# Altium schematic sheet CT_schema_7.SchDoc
size 277 x 170 mm
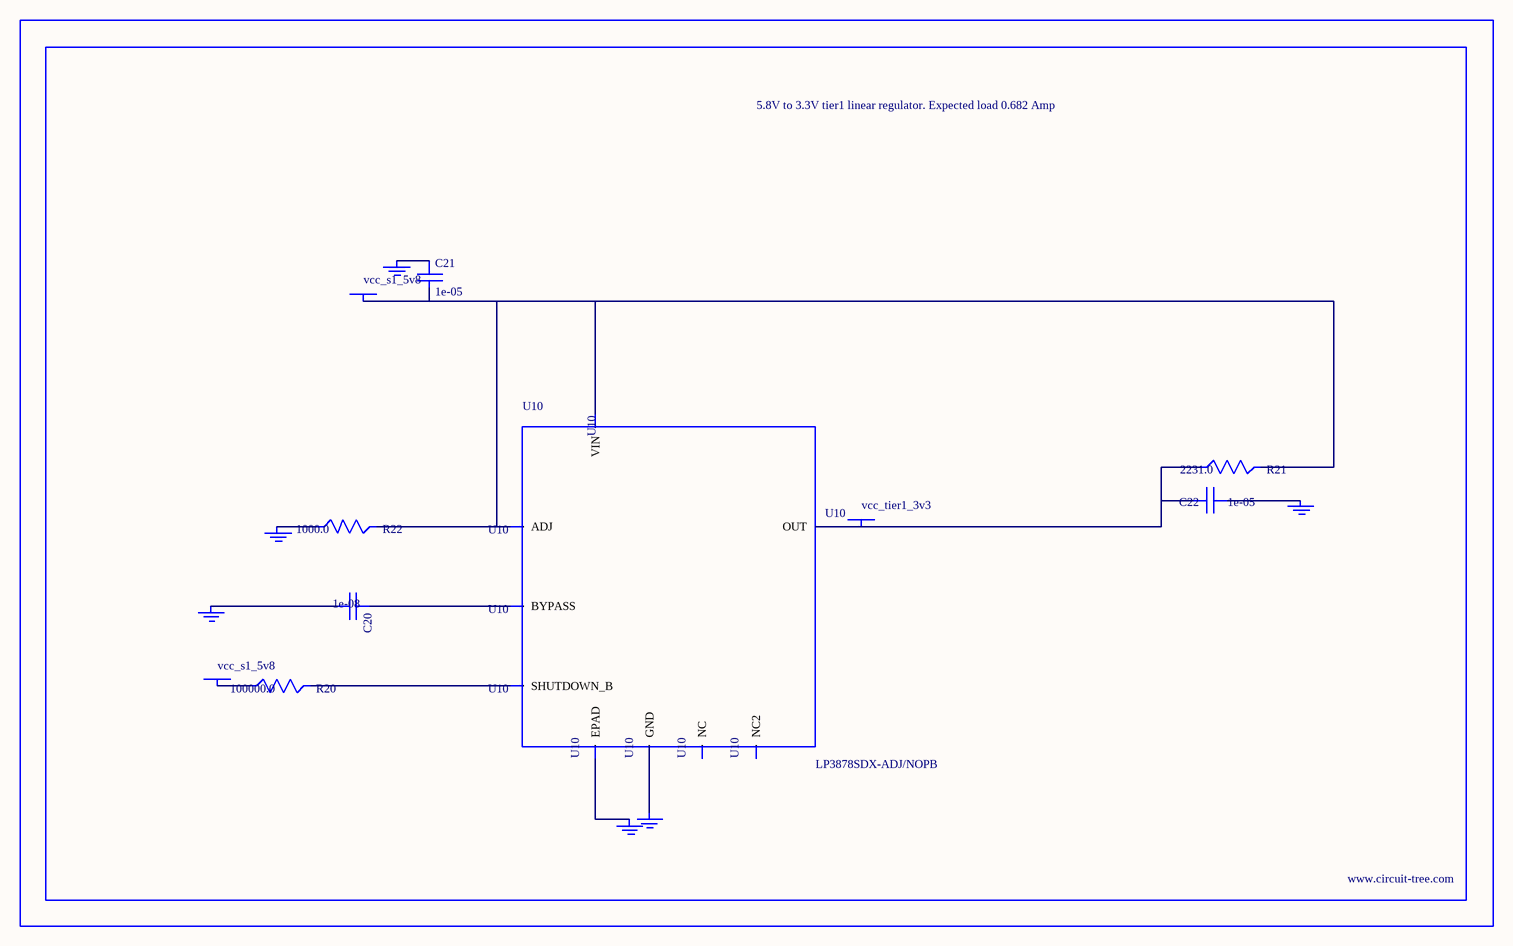
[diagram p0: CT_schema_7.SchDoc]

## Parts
BORDER6  (no value)
C20  1e-08  [C0402]
C21  1e-05  [C1206]
C22  1e-05  [C1210]
GND_INSTANCE_6_0  (no value)
GND_INSTANCE_6_1  (no value)
GND_INSTANCE_6_2  (no value)
GND_INSTANCE_6_3  (no value)
GND_INSTANCE_6_4  (no value)
GND_INSTANCE_6_5  (no value)
POWER_INSTANCE_6_0  vcc_s1_5v8
POWER_INSTANCE_6_1  vcc_s1_5v8
POWER_INSTANCE_6_2  vcc_tier1_3v3
R20  100000.0  [R0603]
R21  2231.0  [R0603]
R22  1000.0  [R0603]
U10  LP3878SDX-ADJ/NOPB  [WSON-8]

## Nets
NetC20_1: C20.1 U10.1(BYPASS)
NetC20_2: C20.2 GND_INSTANCE_6_0.0(GND)
NetC21_1: C21.1 GND_INSTANCE_6_1.0(GND)
NetC21_2: C21.2 POWER_INSTANCE_6_0.0(PWR) R21.2 R22.2 U10.4(VIN) U10.6(ADJ)
NetC22_1: C22.1 GND_INSTANCE_6_2.0(GND)
NetC22_2: C22.2 POWER_INSTANCE_6_2.0(PWR) R21.1 U10.5(OUT)
NetGND_INSTANCE_6_3_0: GND_INSTANCE_6_3.0(GND) R22.1
NetGND_INSTANCE_6_4_0: GND_INSTANCE_6_4.0(GND) U10.PAD(EPAD)
NetGND_INSTANCE_6_5_0: GND_INSTANCE_6_5.0(GND) U10.3(GND)
NetPOWER_INSTANCE_6_1_0: POWER_INSTANCE_6_1.0(PWR) R20.1
NetR20_2: R20.2 U10.8(SHUTDOWN_B)

Not connected (* = marked no-connect by the designer): U10 2(NC) 7(NC2)

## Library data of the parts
BORDER6 = BORDER_PAGE6
C20 = C0402C103K3RAC
C21 = C1206C106K3RACTU
C22 = GRM32DR61E106MA12L
GND_INSTANCE_6_0-GND_INSTANCE_6_5 = GND
POWER_INSTANCE_6_0-POWER_INSTANCE_6_2 = PWR
R20 = RC0603JR-07100KL
R21 = R21
R22 = RC0603JR-071KL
